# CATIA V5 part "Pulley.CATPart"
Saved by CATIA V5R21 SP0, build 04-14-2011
Part number: Pulley
Bounding box of the stored display mesh (mm): x -40.838 to 40.838, y -33 to 33, z -40.838 to 40.838
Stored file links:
  D:\CATIA V5R21 E-RESOURCES\CATIA-V5R21\catia-v5r21-Prts\c14_catia_v5r21_prt\c14-catia-v5r21-figr-14-26 & 27\Part & Asm\Pulley.CATPart
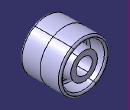
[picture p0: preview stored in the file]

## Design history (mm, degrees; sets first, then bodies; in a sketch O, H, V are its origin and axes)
Body1 (main body)
  Sketch1 on yz-plane, origin (0, 0, 0), H (0, 1, 0), V (0, 0, 1)
    line L1 (0, 13.45) -> (31.5, 13.45)
    point P1 (0, 13.45)
    point P2 (31.5, 13.45)
    line L2 (31.5, 13.45) -> (31.5, 22)
    point P3 (31.5, 22)
    line L3 (31.5, 22) -> (6, 24)
    point P4 (6, 24)
    line L4 (6, 24) -> (6, 33)
    point P5 (6, 33)
    line L5 (6, 33) -> (33, 35)
    point P6 (33, 35)
    line L6 (33, 35) -> (33, 41)
    point P7 (33, 41)
    line L7 (33, 41) -> (0, 41)
    point P8 (0, 41)
    point P9 (0, 41)
    point P10 (-33, 41)
    line L8 (-33, 41) -> (0, 41)
    point P11 (-33, 35)
    line L9 (-33, 35) -> (-33, 41)
    point P12 (-6, 33)
    line L10 (-6, 33) -> (-33, 35)
    point P13 (-6, 24)
    line L11 (-6, 24) -> (-6, 33)
    point P14 (-31.5, 22)
    line L12 (-31.5, 22) -> (-6, 24)
    point P15 (-31.5, 13.45)
    line L13 (-31.5, 13.45) -> (-31.5, 22)
    point P16 (0, 13.45)
    line L14 (0, 13.45) -> (-31.5, 13.45)
    length L1 = 31.5
    distance L1 H = 13.45
    distance P4 H = 24
    distance P3 H = 22
    distance L4 V = 6
    distance P5 H = 33
    distance P6 H = 35
    distance V L6 = 33
    distance L7 H = 41
    coincidence: P1 V, P8 V, P1 P16, P8 P9
    horizontal: L1 H, L7 H
    vertical: L2 V, L4 V, L6 V
    symmetry: P8 P9 V, P7 P10 V, L7 L8 V, P6 P11 V, L6 L9 V, P5 P12 V, L5 L10 V, P4 P13 V, L4 L11 V, P3 P14 V, L3 L12 V, P2 P15 V, L2 L13 V, P1 P16 V, L1 L14 V
  Shaft1: profile Sketch1, axis Sketch1.H, angle 360
  Fillet1: radius 3, on 4 faces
